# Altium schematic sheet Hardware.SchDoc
size 431 x 279 mm; Date: Not shown in title block; ApprovedBy: Not shown in title block; CheckedBy: Not shown in title block; Author: Not shown in title block; CompanyName: Not shown in title block; Engineer: Not shown in title block; Organization: Not shown in title block; Address1: Not shown in title block; Address2: Not shown in title block; Address3: Not shown in title block; Address4: Not shown in title block; DocumentNumber: 1; Revision: Use project parameter SCH_Rev; SheetNumber: 1; SheetTotal: 1; PageSetup: Record=PageOptions|CenterHorizontal=True|CenterVertical=True|PrintScale=1.00|XCorrection=1.00|YCorrection=1.00|PrintKind=0|BorderSize=5000000|LeftOffset=0|BottomOffset=0|Orientation=2|PaperLength=1000|PaperWidth=1000|Scale=100|PaperSource=15|PrintQuality=600|MediaType=1|DitherType=10|PaperKind=Letter|PrintScaleMode=1
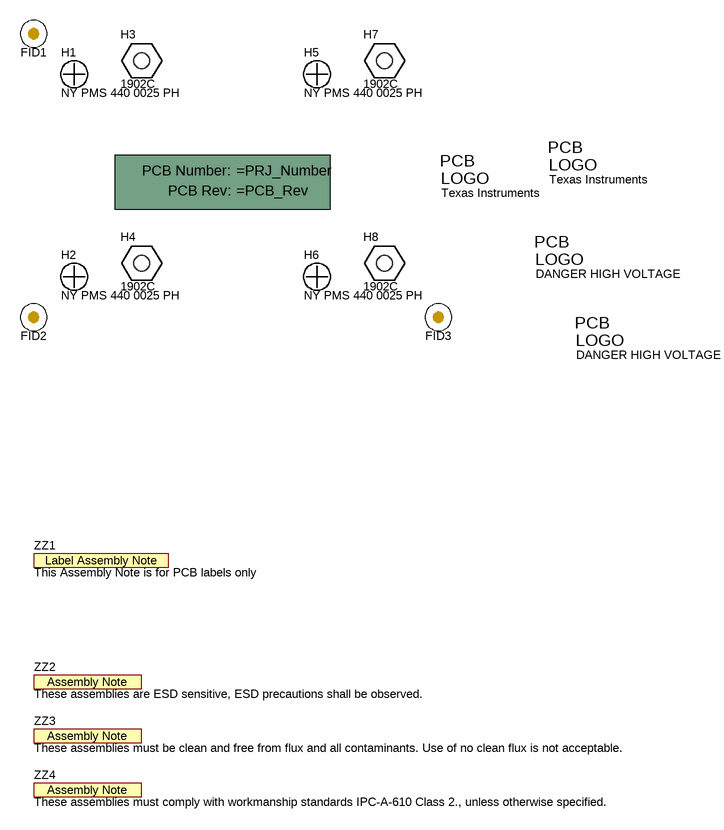
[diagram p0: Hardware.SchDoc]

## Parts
(Parts that share a designator on the sheet are numbered #1, #2 ... from top to bottom, then left to right.)
!PCB1  Printed Circuit Board  (value not drawn)  (mechanical)
FID1  Fiducial  [Fiducial10-20]  (value not drawn)
FID2  Fiducial  [Fiducial10-20]  (value not drawn)
FID3  Fiducial  [Fiducial10-20]  (value not drawn)
H1  NY PMS 440 0025 PH  [NY PMS 440 0025 PH]
H2  NY PMS 440 0025 PH  [NY PMS 440 0025 PH]
H3  1902C  [Keystone_1902C]
H4  1902C  [Keystone_1902C]
H5  NY PMS 440 0025 PH  [NY PMS 440 0025 PH]
H6  NY PMS 440 0025 PH  [NY PMS 440 0025 PH]
H7  1902C  [Keystone_1902C]
H8  1902C  [Keystone_1902C]
Logo1#1  Texas Instruments  [TI_Stacked_Overlay_Small]  (no BOM)
Logo1#2  Texas Instruments  [TI_Stacked_Overlay_Small]  (no BOM)
Logo2  DANGER HIGH VOLTAGE  [IEC_HighVoltage_Small]  (no BOM)
Logo3  DANGER HIGH VOLTAGE  [IEC_HighVoltage_Small]  (no BOM)
ZZ1  This Assembly Note is for PCB labels only  [AssemblyNoteLabel]  (no BOM)
ZZ2  These assemblies are ESD sensitive, ESD precautions shall be observed.  [AssemblyNote]  (no BOM)
ZZ3  These assemblies must be clean and free from flux and all contaminants. Use of no clean flux is not acceptable.  [AssemblyNote]  (no BOM)
ZZ4  These assemblies must comply with workmanship standards IPC-A-610 Class 2., unless otherwise specified.  [AssemblyNote]  (no BOM)

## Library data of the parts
!PCB1 = PCB: Manufacturer: Any; SymbolCreator: a0412235
FID1-FID3 = Fiducial: Fiducial mark.  There is nothing to buy or mount.; SymbolCreator: codlsc
H1 H2 H5 H6 = NY PMS 440 0025 PH: Machine Screw, Round, #4-40 x 1/4, Nylon, Philips panhead; Manufacturer: B&F Fastener Supply; CompType: Hardware; SymbolCreator: codlsc; U/M: EA
H3 H4 H7 H8 = 1902C: Standoff, Hex, 0.5"L #4-40 Nylon; Manufacturer: Keystone; CompType: Hardware
Logo1#1 Logo1#2 = TI_Logo: Texas Instrument Corporate Signature; SymbolCreator: codlsc
Logo2 Logo3 = IEC_HighVoltage: IEC 61010-1 High Voltage Warning; SymbolCreator: a0412235
ZZ1 = AssemblyNoteLabel: SymbolCreator: a0412235
ZZ2-ZZ4 = AssemblyNote: SymbolCreator: codlsc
